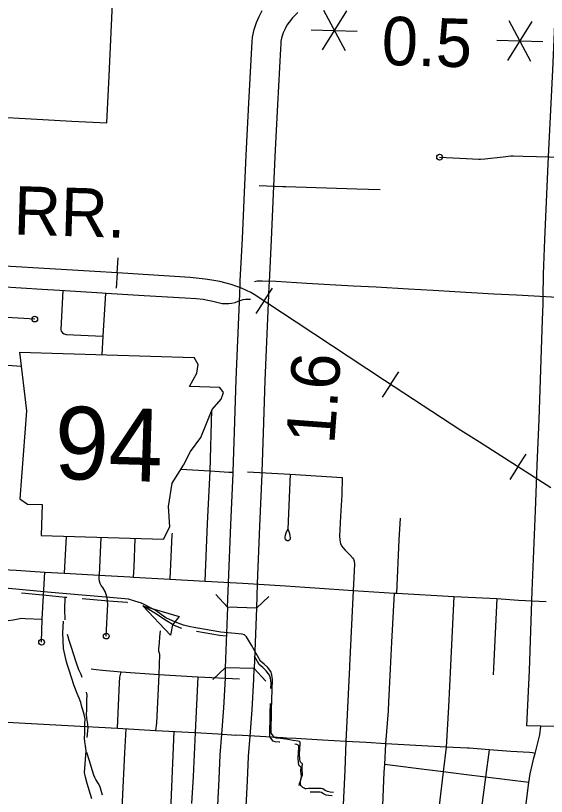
# Model space of a CAD drawing. Extents: x 653372 to 905732, y 627442 to 787275.
# Drawn here: x 684356 to 688975, y 735524 to 742323 of the extents above; entities that cross this region are included whole.
import ezdxf

# ---------------------------------------------------------------- set-up
doc = ezdxf.new("R2010")
doc.units = 0
for name, color, linetype in [('10', 7, 'Continuous'), ('21', 7, 'Continuous'), ('33', 7, 'Continuous'), ('34', 7, 'Continuous'), ('37', 7, 'Continuous'), ('40', 7, 'Continuous'), ('43', 7, 'Continuous'), ('48', 7, 'Continuous'), ('7', 7, 'Continuous')]:
    doc.layers.add(name, color=color, linetype=linetype)

msp = doc.modelspace()

# ---------------------------------------------------------------- linework, layer by layer
at = {"layer": '10'}
for points in [[(689052.3, 736132.5), (688803.8, 736139.7), (688828.2, 736620.5), (688849, 737224.5), (688851.6, 737315.4), (688880.9, 738009.3), (688893, 738325.1), (688895.4, 738407), (688911.5, 738804.9), (688942.3, 739674.4), (688946.8, 739811.1), (688947.2, 739871.6), (688950.9, 740072.6), (688961.6, 740375), (688992.4, 741097), (689032.2, 741848.1), (689059.6, 742519.4)], [(686201.1, 737172.5), (686209.4, 737384.7), (686230.1, 737888.4), (686248.8, 738337.6), (686248.6, 738352.7), (686261.4, 738697.4), (686275.8, 739154.8), (686306, 739901.8), (686310.2, 739980.4), (686311.5, 740013.9), (686329.2, 740382.9), (686352.1, 740849.1), (686366, 741166.6), (686386.7, 741560.4), (686411.1, 742045.8), (686413.7, 742093.6), (686417.8, 742136.8), (686431, 742203.4), (686451.3, 742263.8), (686475.1, 742316.9), (686501.6, 742368.6)], [(686812.5, 742349.8), (686764.6, 742302.7), (686735.3, 742266.5), (686716.3, 742239.4), (686700.6, 742208.7), (686684.3, 742172.6), (686673.1, 742139.2), (686665.5, 742100.7), (686663.1, 742075.1), (686660.8, 742032.7), (686636.3, 741547.6), (686615.7, 741154.6), (686601.8, 740837.6), (686578.9, 740370.8), (686561.3, 740003.3), (686560, 739969), (686555.7, 739890), (686525.6, 739145.8), (686511.2, 738688.9), (686498.7, 738350), (686498.9, 738334.3), (686479.8, 737878), (686459.2, 737374.8), (686451, 737162.7), (686201.1, 737172.5)], [(686201.1, 737172.5), (686180.9, 736642.9)], [(686451, 737162.7), (686430.8, 736637.2)], [(686430.8, 736637.2), (686180.9, 736642.9), (686178.8, 736553.3), (686165.5, 736293.7), (686146.6, 736066.4), (686134.3, 735886.4), (686124.7, 735672.5), (686112.7, 735448.9), (686093.9, 735055.6), (686093.1, 734996.5), (686092.4, 734944.6), (686096.8, 734845.1), (686357.3, 734829.9)], [(686357.3, 734829.9), (686349.6, 734864.9), (686344.5, 734903.6), (686342.5, 734948.5), (686343.1, 734993.1), (686343.8, 735047.9), (686362.4, 735436.2), (686374.4, 735660.2), (686383.9, 735872.2), (686395.9, 736047.5), (686415, 736276.9), (686428.7, 736544), (686430.8, 736637.2)]]:
    msp.add_lwpolyline(points, dxfattribs=at)
at = {"layer": '21'}
for p, q in [((684389.7, 739391.8), (684450.6, 738882.2)), ((685943.7, 739285.9), (685910.4, 739345.4)), ((685933, 739210.1), (685943.7, 739285.9)), ((685870.2, 739093.5), (685933, 739210.1)), ((686132.3, 739085.6), (685870.2, 739093.5)), ((686164.9, 739042.3), (686132.3, 739085.6)), ((686146.2, 738983.6), (686164.9, 739042.3)), ((686067.3, 738892.9), (686146.2, 738983.6)), ((684450.6, 738882.2), (684393.7, 738113.8)), ((686021.7, 738784.3), (686067.3, 738892.9)), ((685966.9, 738650.5), (686021.7, 738784.3)), ((685878.6, 738526.2), (685966.9, 738650.5)), ((685815.8, 738409.6), (685878.6, 738526.2)), ((685718, 738251.8), (685815.8, 738409.6)), ((685686.5, 738049.6), (685718, 738251.8)), ((684393.7, 738113.8), (684460, 738069.5)), ((684460, 738069.5), (684586.9, 738065.7)), ((684586.9, 738065.7), (684578.7, 737795.1)), ((685698.1, 737871.5), (685686.5, 738049.6)), ((685644.1, 737763.1), (685698.1, 737871.5)), ((684578.7, 737795.1), (685644.1, 737763.1))]:
    msp.add_line(p, q, dxfattribs=at)
msp.add_lwpolyline([(684389.7, 739391.8), (685910.4, 739345.4)], dxfattribs=at)
at = {"layer": '33'}
for points in [[(683867.4, 741458), (684492.7, 741423.4), (684846, 741404.8), (685148.6, 741388.6), (685169.7, 741799.8), (685179.3, 741988.6), (685211.5, 742685)], [(688045.7, 741090.4), (688277, 741077.6), (688386.9, 741072), (688402.4, 741072.3), (688440.5, 741076.6), (688600.3, 741094.3), (688665.6, 741100.8), (688685.7, 741101.8), (688774, 741099.1), (689117.3, 741091.1)], [(686476.9, 740843.4), (686677.8, 740836.1), (686708.8, 740835.2), (687324.2, 740814.2), (687527.8, 740810)], [(684035.7, 739975.7), (684587.5, 739941.6), (684737.4, 739932.6), (685108.3, 739909.5), (685143.8, 739906.9), (685475.1, 739886.6), (685832, 739865.4), (685927.9, 739859.7), (685987.2, 739853.8), (686029.7, 739845.5), (686071.4, 739836.5), (686117.9, 739824.6), (686154.1, 739817.3), (686168.7, 739815.4), (686188.3, 739814.8), (686211.4, 739816.2), (686235.3, 739819.7), (686267.7, 739825), (686293.2, 739835.5), (686318.7, 739845.2), (686337.7, 739850.2), (686356, 739853.2), (686371.4, 739854.1), (686399.4, 739855.4)], [(686436.4, 740008.6), (686457.6, 740012.6), (686478.1, 740014.8), (686500.9, 740014.7), (686622.1, 740011), (686890, 739993.3), (687293.5, 739969.8), (687494, 739960.9), (687774.7, 739943.9), (687991, 739931.2), (688179.2, 739919.8), (688518.9, 739899.9), (688715.5, 739890.6), (689072.2, 739870.1)], [(684767, 739930.8), (684749.7, 739590.7), (684753.6, 739574.9), (684762.7, 739560.7), (684777.2, 739550.7), (684796.2, 739546.7), (685115, 739531)], [(685136.9, 739907.3), (685115, 739531), (685107.4, 739369.9)], [(684522.3, 739680.2), (683793.8, 739722.9)], [(684404.5, 739267.7), (684207.7, 739280.8), (683937.1, 739295.9), (683775.3, 739305.3)], [(686005.9, 737399), (686026.5, 737899.3), (686048.5, 738354.8), (686064.7, 738889.9)], [(686249.1, 738343.1), (686212.4, 738345.3), (686048.5, 738354.8), (685795.3, 738371.5)], [(686373.6, 738351.3), (686745.1, 738329.9), (687199.4, 738301)], [(686745.1, 738329.9), (686726.3, 737851)], [(687199.4, 738301), (687194.1, 738150.5), (687184.5, 737964.4), (687175.2, 737790.7), (687177.3, 737757.7), (687184.8, 737723.3), (687194.9, 737703.9), (687204.8, 737690.1), (687223.4, 737668.4), (687266, 737626.9), (687288.6, 737602.6), (687295.4, 737590.8), (687301, 737573), (687306.5, 737545.1), (687294.6, 737315.9)], [(687673.9, 737293.9), (687694.9, 737758.5), (687705, 737945.5)], [(685717.2, 737815.7), (685714.7, 737803.7), (685698.9, 737415.9)], [(686726.3, 737851), (686729.7, 737838.4), (686738.8, 737813), (686743.1, 737793.2), (686744.9, 737776.2), (686744.1, 737766.4), (686741.2, 737759.3), (686735.2, 737753.6), (686729.8, 737750.2), (686724.8, 737749), (686718.1, 737750.1), (686709.8, 737755.3), (686703.8, 737762.6), (686701.3, 737771.2), (686701.2, 737782.4), (686703.9, 737798), (686711.7, 737819.2), (686726.3, 737851)], [(678446, 737776.3), (678708.1, 737768), (678973.3, 737754.4), (679189, 737743), (679480.7, 737731.8), (679771.4, 737717.1), (680264.4, 737692.4), (680538.5, 737680.1), (680746.3, 737672.5), (681085.2, 737653.3), (681502.3, 737630.4), (681663.9, 737623.4), (682034.5, 737607.2), (682461.1, 737586.3), (682533.6, 737583.3), (682804.7, 737569.6), (682891.5, 737565.7), (683099.8, 737556.1), (683403.6, 737540.7), (683706.6, 737525.1), (684359.4, 737493.2), (684610.8, 737477.3), (684782.6, 737468), (685083, 737451.1)], [(684782.6, 737468), (684797.8, 737788.6)], [(685097.7, 737779.6), (685083, 737451.1)], [(685383.3, 737433.7), (685386.6, 737520.4), (685396.5, 737770.6)], [(684581.8, 736867.3), (684588.5, 737067.3), (684610.8, 737477.3)], [(685144.8, 736919.9), (685157.3, 737197.3), (685156, 737224.6), (685152.1, 737255.5), (685143.8, 737281.7), (685134.1, 737308.5), (685114.1, 737341.9), (685100.7, 737360.5), (685092.1, 737378.2), (685086.4, 737397.9), (685082.9, 737419.7), (685083, 737451.1)], [(685083, 737451.1), (685349.1, 737435.5), (685383.3, 737433.7), (685698.9, 737415.9), (686005.9, 737399), (686167.4, 737389.5), (686334.3, 737379.8)], [(686334.3, 737379.8), (686704.1, 737358.5), (686873.9, 737346.4), (686960.6, 737341.3), (687294.6, 737315.9), (687653.9, 737294.5), (687673.9, 737293.9), (688168.7, 737265.7), (688358.2, 737254.9), (688542.9, 737246.2), (688731.6, 737234), (688973.9, 737220.6)], [(687294.6, 737315.9), (687262.7, 736662.3), (687262.3, 736649.1), (687229.5, 736001.9), (687221.1, 735752.2), (687204, 735390), (687188.8, 735032), (687180.2, 734855.9), (687173.8, 734661.9)], [(687520.2, 734645.8), (687564.3, 735734.9), (687568.8, 735802.5), (687577, 735980.9), (687599.9, 736269.4), (687604.1, 736348.6), (687610, 736456.3), (687618, 736633.9), (687629.5, 736867.1), (687653.9, 737294.5)], [(688168.7, 737265.7), (688139.7, 736664.5), (688124.7, 736302.6), (688102.6, 735953.9), (688075.7, 735737.8), (687942.2, 734616.2)], [(688542.9, 737246.2), (688516.3, 736640.4), (688513.4, 736582.4)], [(684248.1, 737050.2), (684334.5, 737062.3), (684392.8, 737073.9), (684410.4, 737074.7), (684439, 737073.9), (684588.5, 737067.3)], [(685615.1, 736965.2), (685609.3, 736914.6), (685605.6, 736860.1), (685599.2, 736810), (685600.6, 736787.5), (685605.7, 736772.7), (685607.4, 736759.3), (685602.3, 736584.2), (685581.1, 736162.4), (685574.3, 736098.3)], [(685013.4, 736635.7), (685058.2, 736628), (685111.2, 736622.9), (685274.1, 736609.6), (685602.3, 736584.2), (685940.6, 736566), (686303.8, 736548.6)], [(685243, 736117), (685259.1, 736512.5), (685264, 736561.3), (685274.1, 736609.6)], [(685940.6, 736566), (685917.9, 736079), (685900.4, 735696.7), (685887, 735461.4)], [(681018.9, 736334.4), (681652.8, 736299.2), (681796, 736290.6), (681951.4, 736281.9), (682099.3, 736274.5), (682638.8, 736249.8), (683022.2, 736227.5), (683155.4, 736223.5), (683315.7, 736220.4), (683437.5, 736216.7), (683560.3, 736211.3), (683618, 736207.3), (683645.9, 736205.9), (684121.1, 736178.2), (684811.3, 736140.9), (685243, 736117), (685574.3, 736098.3), (685917.9, 736079), (686117.6, 736070), (686271.3, 736056.9)], [(685259.2, 734774.7), (685264.4, 734962.2), (685270.8, 735135), (685276, 735305.8), (685285.1, 735478.1), (685305.3, 735901.9), (685319.2, 736111.7)], [(688699.2, 734696.5), (688725.4, 734899.4), (688775.6, 735276.4), (688822.8, 735643.5), (688834.5, 735720.9), (688853.2, 735807.5), (688865.4, 735859.4), (688876.6, 735896.8), (688904.5, 736000.9), (688917.7, 736060.4), (688926.8, 736136.1)], [(688876.6, 735896.8), (688854.2, 735902.7), (688827.8, 735907.5), (688665.1, 735915.2), (688476.8, 735930.5), (688304.7, 735943), (688293.9, 735943.3), (688287.4, 735943.5), (688102.6, 735953.9), (687840.1, 735968.2), (687577, 735980.9), (687408, 735992), (687229.5, 736001.9), (687028.1, 736013), (686795.5, 736027.3), (686713.2, 736032), (686680.3, 736034.9), (686434, 736048.4), (686271.3, 736056.9)], [(688476.8, 735930.5), (688445.7, 735691.3), (688298, 734569.1)], [(688822.8, 735643.5), (688635, 735667), (688445.7, 735691.3), (688255.9, 735715), (688075.7, 735737.8), (687819.4, 735770), (687568.8, 735802.5)]]:
    msp.add_lwpolyline(points, dxfattribs=at)
for centre in [(688045.7, 741090.4), (685144.8, 736919.9), (684581.8, 736867.3)]:
    msp.add_circle(centre, 25, dxfattribs=at)
at = {"layer": '34'}
msp.add_lwpolyline([(685677.5, 735095.2), (685681.6, 735112.2), (685688.1, 735149), (685698.8, 735229.5), (685706.9, 735325.6), (685710.7, 735467.2), (685736.1, 736090)], dxfattribs=at)
at = {"layer": '37'}
for points in [[(686201.1, 737172.4), (686099.3, 737282.5)], [(686561, 737264.6), (686451, 737162.8)], [(686071.9, 736540.5), (686180.9, 736643.6)], [(686430.8, 736636.5), (686533.8, 736527.5)]]:
    msp.add_lwpolyline(points, dxfattribs=at)
at = {"layer": '40'}
for p, q in [((685240.3, 740081.9), (685248.5, 740213.7)), ((685240.3, 740081.9), (685232.1, 739950.2)), ((686518.2, 739839), (686591.1, 739949.1)), ((686518.2, 739839), (686445.4, 739728.9)), ((687619.1, 739110.7), (687691.3, 739221.2)), ((687619.1, 739110.7), (687546.9, 739000.2)), ((688727.7, 738394.2), (688798.8, 738505.4)), ((688727.7, 738394.2), (688656.6, 738283))]:
    msp.add_line(p, q, dxfattribs=at)
msp.add_lwpolyline([(689013.3, 738211.5), (688392.3, 738608.6), (688232.1, 738710.3), (687565.8, 739145.6), (686797.5, 739654.2), (686432.2, 739896), (686403.3, 739911.5), (686366.8, 739930.4), (686321.7, 739948.7), (686280.5, 739965.4), (686233.1, 739980.7), (686189.5, 739992.9), (686132.7, 740006.9), (686062.8, 740019.8), (686004.4, 740029.3), (685953.6, 740034.7), (685874.6, 740041.3), (685286.2, 740079.1), (685094.5, 740091), (683817.9, 740168)], dxfattribs=at)
msp.add_lwpolyline([(689013.3, 738211.5), (688392.3, 738608.6), (688232.1, 738710.3), (687565.8, 739145.6), (686797.5, 739654.2), (686432.2, 739896), (686403.3, 739911.5), (686366.8, 739930.4), (686321.7, 739948.7), (686280.5, 739965.4), (686233.1, 739980.7), (686189.5, 739992.9), (686132.7, 740006.9), (686062.8, 740019.8), (686004.4, 740029.3), (685953.6, 740034.7), (685874.6, 740041.3), (685286.2, 740079.1), (685094.5, 740091), (683817.9, 740168)], dxfattribs=at)
at = {"layer": '43'}
for p, q in [((685462.7, 737184.2), (685779, 737089.1)), ((685705.3, 736927.4), (685462.7, 737184.2)), ((685779, 737089.1), (685720.9, 737018.6)), ((685720.4, 737017.5), (685705.3, 736927.4))]:
    msp.add_line(p, q, dxfattribs=at)
for points in [[(686326.9, 736937.7), (686142.8, 736955.1), (685925.9, 736992.1), (685863.5, 737004.1), (685816.4, 737015.7), (685747.8, 737041.5), (685664.2, 737079.6), (685569.6, 737146.8), (685452.5, 737205.2), (685392.4, 737225), (685338.7, 737241.9), (685176.5, 737255.2), (684799.5, 737287.9), (684633.2, 737302.9), (683922.5, 737370)], [(684802.4, 737256.1), (684788.2, 737257.3), (684622, 737272.2), (684408.1, 737292.4)], [(684788.6, 737062.7), (684784.9, 737155.1), (684788.2, 737257.3)], [(685131.1, 737227.5), (684933.9, 737244.6)], [(685328.4, 737210.9), (685327.5, 737211.2), (685165.2, 737224.6), (685131.1, 737227.5)], [(685802.7, 736986), (685736.5, 737010.8), (685670.5, 737051.4), (685568.2, 737120.9), (685462.7, 737184.2)], [(685020.1, 735502.4), (685007.7, 735539), (684980.1, 735635.1), (684963.1, 735690.6), (684955.6, 735732.8), (684970.5, 735920), (684965.1, 735964.7), (684959.4, 735998.6), (684956.7, 736029.7), (684959, 736071.6), (684959.5, 736106.9), (684958.7, 736156.1), (684961.3, 736199.8), (684953.7, 736238.3), (684929.1, 736316.3), (684923.4, 736343), (684909.5, 736380.2), (684891, 736419.6), (684866.5, 736488), (684822.4, 736623.1), (684812.9, 736648.5), (684805.4, 736674.6), (684796.6, 736706.5), (684773.8, 736811.5), (684768.4, 736949), (684771.7, 737051.2)], [(684936.4, 736558.4), (684926, 736586.3), (684907.5, 736625.7), (684883.1, 736694.1), (684839, 736829.3), (684829.5, 736854.6), (684822, 736880.8), (684813.1, 736912.6), (684808.7, 736932.7)], [(686191.4, 736918.8), (686131.5, 736924.4), (685931.7, 736958.5)], [(687121.2, 735558.4), (687093.5, 735561.2), (687069.7, 735566.4), (687056.9, 735571.3), (687042.4, 735580.8), (687030.3, 735588.3), (687014.2, 735591.4), (686987.7, 735592.2), (686905.4, 735591.7), (686885.3, 735589.7), (686876.9, 735590.6), (686866, 735594.2), (686856.5, 735601), (686847.7, 735609.6), (686840.8, 735616.9), (686836.6, 735625.5), (686835.6, 735635.9), (686835.3, 735649.4), (686839.1, 735667.4), (686845.5, 735687.9), (686852.1, 735712.3), (686853.9, 735730.4), (686851.3, 735749.9), (686850.1, 735774.5), (686850.5, 735790), (686853.4, 735799.6), (686851.7, 735805.5), (686849.9, 735810), (686842.9, 735814.1), (686836, 735821.5), (686831.1, 735832), (686829, 735848.2), (686827.1, 735890.3), (686833, 735980.3), (686832.1, 735995.2), (686827.8, 736000.5), (686815, 736006), (686771.2, 736011.2), (686708.8, 736022.1), (686659.9, 736028.1), (686626.3, 736031.1), (686609.8, 736035.5), (686588.7, 736062), (686580.1, 736077.1), (686583.5, 736278.3), (686590.8, 736541.3), (686586.8, 736582.8), (686576.7, 736610.9), (686548.1, 736649.3), (686519.8, 736676.3), (686488.3, 736701.9), (686407.8, 736841.4), (686366, 736913.8), (686348.4, 736929.8), (686326.9, 736937.7)], [(686578.3, 736464.8), (686579.5, 736510.7), (686575.6, 736552.2), (686565.5, 736580.3), (686536.9, 736618.7), (686508.6, 736645.7), (686477, 736671.2), (686434.9, 736744.2)], [(684980, 736037.6), (684987, 736126.2), (684981.6, 736170.9), (684975.9, 736204.7), (684973.2, 736235.9), (684975.5, 736277.8), (684976.1, 736313), (684975.2, 736362.2), (684977.8, 736405.9), (684972.7, 736431.7)], [(686656, 735996.6), (686648.6, 735997.5), (686615.1, 736000.4), (686598.6, 736004.8), (686577.4, 736031.3), (686568.8, 736046.4), (686572.3, 736247.7), (686574.6, 736332.9)], [(686824.1, 735618.4), (686824.1, 735618.8), (686827.9, 735636.8), (686834.3, 735657.3), (686840.8, 735681.7), (686842.7, 735699.7), (686840, 735719.2), (686838.8, 735743.8), (686839.3, 735759.3), (686842.2, 735768.9), (686840.4, 735774.8), (686838.6, 735779.4), (686831.6, 735783.5), (686824.7, 735790.8), (686819.9, 735801.3), (686817.8, 735817.5), (686815.8, 735859.6), (686821.7, 735949.6), (686820.9, 735964.5), (686816.5, 735969.8), (686803.8, 735975.4), (686786.6, 735977.4)], [(685110.9, 735535.8), (685106.9, 735553.8), (685101.7, 735576.6), (685096, 735596.4), (685088.9, 735613.1), (685074.8, 735638.9), (685054.8, 735670.9), (685045.8, 735687.5), (685036.6, 735708.5), (685024.3, 735745.1), (684996.6, 735841.3), (684979.6, 735896.7), (684977.9, 735906.4)], [(687110, 735527.8), (687082.2, 735530.5), (687058.5, 735535.8), (687045.7, 735540.7), (687031.1, 735550.2), (687019.1, 735557.6), (687003, 735560.7), (686976.5, 735561.5), (686918.8, 735561.2)]]:
    msp.add_lwpolyline(points, dxfattribs=at)
at = {"layer": '48'}
for p, q in [((687234.5, 742364.7), (687024.2, 742024.5)), ((687034.6, 742370.7), (687224.1, 742018.5)), ((688648.6, 742279.3), (688838.1, 741927)), ((688848.5, 742273.3), (688638.2, 741933)), ((686929.5, 742200.6), (687329.3, 742188.6)), ((688543.4, 742109.2), (688943.2, 742097.1))]:
    msp.add_line(p, q, dxfattribs=at)
at = {"layer": '7'}
msp.add_circle((684522.3, 739680.2), 25, dxfattribs=at)

# ---------------------------------------------------------------- texts
at = {"layer": '21'}
msp.add_text('94', height=633.6, rotation=358.28003, dxfattribs=at).set_placement((684687.2, 738290.3))
at = {"layer": '40'}
msp.add_text('RR.', height=422.4, rotation=358.28003, dxfattribs=at).set_placement((684335.4, 740417.3))
at = {"layer": '48'}
for s, rotation, p in [('0.5', 358.28003, (687537.5, 741895)), ('1.6', 85.76398, (687129.6, 738585.5))]:
    msp.add_text(s, height=422.4, rotation=rotation, dxfattribs=at).set_placement(p)

doc.saveas('drawing.dxf')
